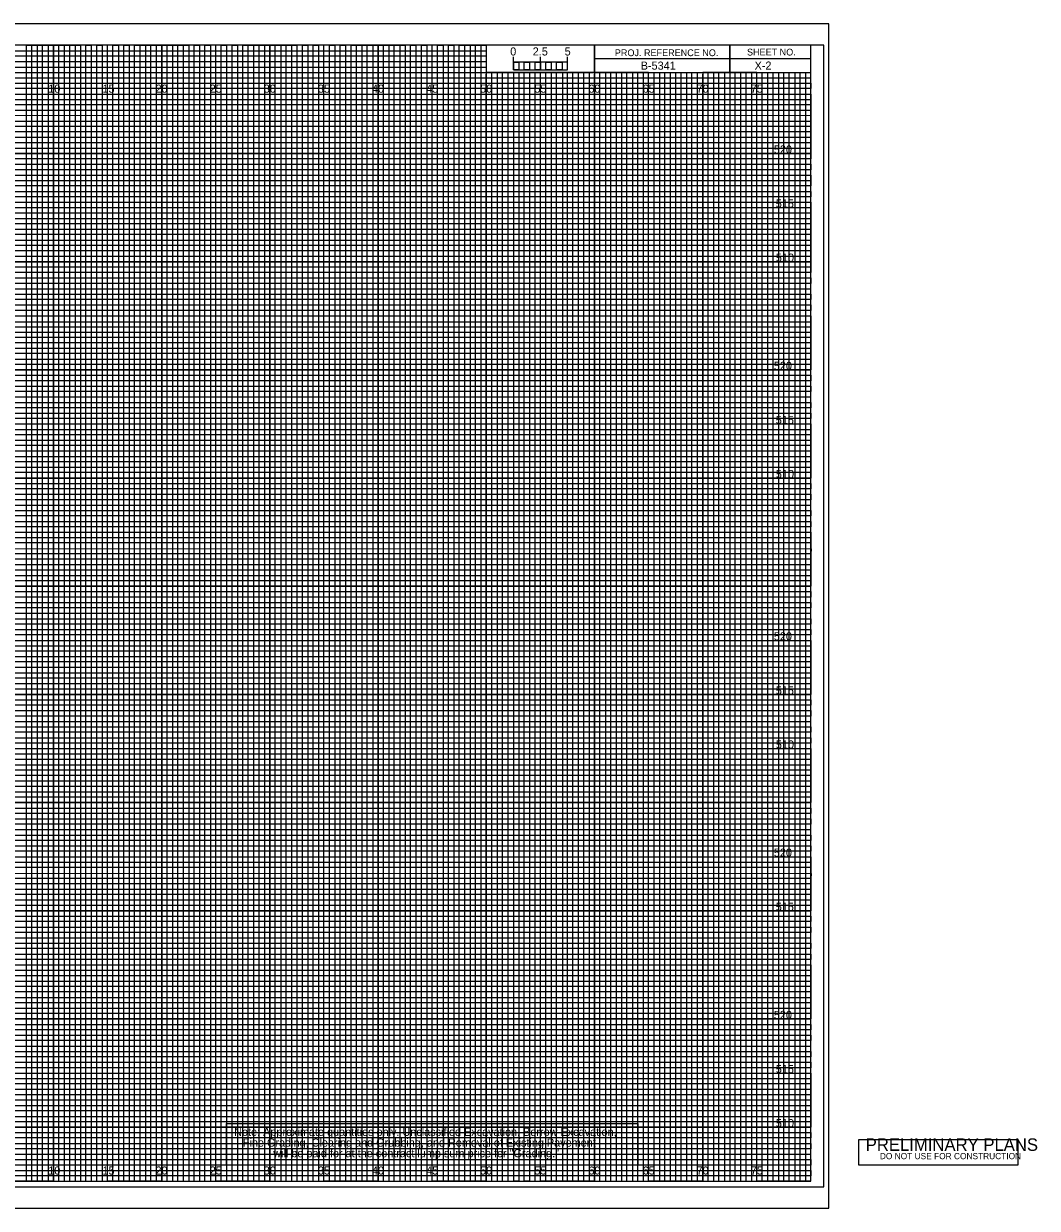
# Model space of a CAD drawing. Extents: x -7 to 181, y -2 to 107.
# Drawn here: x 87.2 to 180.9, y -2.5 to 107 of the extents above; entities that cross this region are included whole.
import ezdxf

# ---------------------------------------------------------------- set-up
doc = ezdxf.new("R2010")
doc.units = 0
for name, color, linetype in [('Prop Grid Mask', 7, 'Continuous'), ('Prop XS Bar Scale Labels', 7, 'Continuous'), ('Prop XS Elevation Labels', 7, 'Continuous'), ('Prop XS Offset Labels', 7, 'Continuous'), ('Prop XS Project Number', 7, 'Continuous'), ('Prop XS Sheet Number', 7, 'Continuous'), ('Prop XSC Text', 7, 'Continuous'), ('Sheet Cross Section CELL', 7, 'Continuous'), ('Sheet Cross Section Grid Major CELL', 7, 'Continuous'), ('Sheet Cross Section Grid Middle CELL', 7, 'Continuous'), ('Sheet Cross Section Grid Minor 1 CELL', 7, 'Continuous'), ('Sheet Cross Section Grid Minor 2 CELL', 7, 'Continuous'), ('Sheet Cross Section Scale CELL', 7, 'Continuous'), ('Sheet Cutting Line CELL', 7, 'Continuous'), ('Sheet DOT Grid CELL', 7, 'Continuous'), ('Sheet Plot Border Inside CELL', 7, 'Continuous'), ('Sheet Plot Border Outside CELL', 7, 'Continuous'), ('Sheet Sticker Preliminary CELL', 7, 'Continuous')]:
    doc.layers.add(name, color=color, linetype=linetype)

msp = doc.modelspace()

# ---------------------------------------------------------------- linework, layer by layer
at = {"layer": 'Prop Grid Mask'}
msp.add_lwpolyline([(105.99, 5.34), (144, 5.34), (144, 1.5), (105.99, 1.5)], close=True, dxfattribs=at)
at = {"layer": 'Sheet Cross Section CELL'}
for p, q in [((152.5, 105), (152.5, 102.5)), ((152.5, 102.5), (152.5, 105)), ((160, 103.75), (140, 103.75)), ((140, 103.75), (140, 102.5)), ((140, 102.5), (160, 102.5))]:
    msp.add_line(p, q, dxfattribs=at)
for points in [[(160, 105), (0, 105), (0, 0), (160, 0)], [(140, 105), (130, 105), (130, 102.52), (140, 102.52)], [(160, 105), (140, 105), (140, 102.5), (160, 102.5)]]:
    msp.add_lwpolyline(points, close=True, dxfattribs=at)
at = {"layer": 'Sheet Cross Section Grid Major CELL'}
for p, q in [((95, 105), (90, 105)), ((90, 105), (90, 0)), ((95, 0), (95, 105)), ((105, 105), (100, 105)), ((100, 105), (100, 0)), ((105, 0), (105, 105)), ((115, 105), (110, 105)), ((110, 105), (110, 0)), ((115, 0), (115, 105)), ((125, 105), (120, 105)), ((120, 105), (120, 0)), ((125, 0), (125, 105)), ((130, 105), (130, 0)), ((135, 0), (135, 102.5)), ((145, 102.5), (140, 102.5)), ((140, 102.5), (140, 0)), ((145, 0), (145, 102.5)), ((155, 102.5), (150, 102.5)), ((150, 102.5), (150, 0)), ((155, 0), (155, 102.5)), ((90, 0), (85, 0)), ((100, 0), (95, 0)), ((110, 0), (105, 0)), ((120, 0), (115, 0)), ((130, 0), (125, 0)), ((140, 0), (135, 0)), ((150, 0), (145, 0)), ((160, 0), (155, 0)), ((160, 0), (160, 0))]:
    msp.add_line(p, q, dxfattribs=at)
for points in [[(0, 100), (160, 100), (160, 95), (0, 95)], [(0, 90), (160, 90), (160, 85), (0, 85)], [(0, 80), (160, 80), (160, 75), (0, 75)], [(0, 70), (160, 70), (160, 65), (0, 65)], [(0, 60), (160, 60), (160, 55), (0, 55)], [(0, 50), (160, 50), (160, 45), (0, 45)], [(0, 40), (160, 40), (160, 35), (0, 35)], [(0, 30), (160, 30), (160, 25), (0, 25)], [(0, 20), (160, 20), (160, 15), (0, 15)], [(0, 10), (160, 10), (160, 5), (0, 5)]]:
    msp.add_lwpolyline(points, dxfattribs=at)
at = {"layer": 'Sheet Cross Section Grid Middle CELL'}
for points in [[(82.5, 0), (87.5, 0), (87.5, 105), (92.5, 105), (92.5, 0), (97.5, 0), (97.5, 105), (102.5, 105), (102.5, 0), (107.5, 0), (107.5, 105), (112.5, 105), (112.5, 0), (117.5, 0), (117.5, 105), (122.5, 105), (122.5, 0), (127.5, 0), (127.5, 105), (129.97, 105), (130, 105), (130, 102.5), (132.5, 102.5), (132.5, 0), (137.5, 0), (137.5, 102.5), (142.5, 102.5), (142.5, 0), (147.5, 0), (147.5, 102.5), (152.5, 102.5), (152.5, 0), (157.5, 0), (157.5, 102.5)], [(0, 102.5), (137.5, 102.5)], [(0, 92.5), (160, 92.5), (160, 97.5), (0, 97.5)], [(0, 82.5), (160, 82.5), (160, 87.5), (0, 87.5)], [(0, 72.5), (160, 72.5), (160, 77.5), (0, 77.5)], [(0, 62.5), (160, 62.5), (160, 67.5), (0, 67.5)], [(0, 52.5), (160, 52.5), (160, 57.5), (0, 57.5)], [(0, 42.5), (160, 42.5), (160, 47.5), (0, 47.5)], [(0, 32.5), (160, 32.5), (160, 37.5), (0, 37.5)], [(0, 22.5), (160, 22.5), (160, 27.5), (0, 27.5)], [(0, 12.5), (160, 12.5), (160, 17.5), (0, 17.5)], [(0, 2.5), (160, 2.5), (160, 7.5), (0, 7.5)]]:
    msp.add_lwpolyline(points, dxfattribs=at)
at = {"layer": 'Sheet Cross Section Grid Minor 1 CELL'}
for p, q in [((0, 104.5), (130, 104.5)), ((130, 104.5), (130, 103.99)), ((130, 103.99), (0, 103.99)), ((0, 103.5), (130, 103.5)), ((130, 102.95), (0, 102.95)), ((130, 103.5), (130, 102.95)), ((0, 102), (160, 102))]:
    msp.add_line(p, q, dxfattribs=at)
for points in [[(0, 101.5), (135, 101.5), (160, 101.5), (160, 101), (0, 101)], [(0, 100.5), (160, 100.5), (160, 99.5), (0, 99.5)], [(0, 99), (160, 99), (160, 98.5), (0, 98.49)], [(0, 98), (160, 98), (160, 97), (0, 97)], [(0, 96.5), (160, 96.5), (160, 96), (0, 96)], [(0, 95.5), (160, 95.5), (160, 94.5), (0, 94.5)], [(0, 94), (160, 94), (160, 93.5), (0, 93.5)], [(0, 93), (160, 93), (160, 92), (0, 92)], [(0, 91.5), (160, 91.5), (160, 91), (0, 91)], [(0, 90.5), (160, 90.5), (160, 89.5), (0, 89.5)], [(0, 89), (160, 89), (160, 88.5), (0, 88.5)], [(0, 88), (160, 88), (160, 86.98), (160, 86.5), (160, 86), (0, 86)], [(0, 87), (160, 87), (160, 86.5), (0, 86.5)], [(0, 85.5), (160, 85.5), (160, 84.5), (0, 84.52)], [(0, 84.52), (160, 84.5), (160, 84), (0, 84)], [(0, 83.5), (160, 83.5), (160, 83), (0, 83)], [(0, 82), (160, 82), (160, 81.5), (0, 81.5)], [(0, 81), (160, 81), (160, 80.5), (0, 80.5)], [(-0.04, 79.45), (160, 79.45), (160, 78.94), (-0.04, 78.94)], [(0, 78.5), (160, 78.5), (160, 78), (0, 78)], [(0, 77), (160, 77), (160, 76.5), (0, 76.5)], [(0, 76), (160, 76), (160, 75.5), (0, 75.5)], [(0, 74.5), (160, 74.5), (160, 74), (0, 74)], [(0, 73.5), (160, 73.5), (160, 73), (0, 73)], [(0, 72), (160, 72), (160, 71.5), (0, 71.5)], [(0, 71), (160, 71), (160, 70.5), (0, 70.5)], [(0, 69.5), (160, 69.5), (160, 68.99), (0, 69)], [(0, 68.5), (160, 68.5), (160, 68), (0, 68)], [(0, 67), (160, 67), (160, 66.5), (0, 66.5)], [(0, 66), (160, 66), (160, 65.5), (0, 65.5)], [(0, 64.5), (160, 64.5), (160, 64), (0, 64)], [(0, 63.5), (160, 63.5), (160, 63), (0, 63)], [(0, 62), (160, 62), (160, 61.5), (0, 61.5)], [(0, 61), (160, 61), (160, 60.5), (0, 60.5)], [(0, 59.5), (160, 59.5), (160, 59), (0, 59)], [(0, 58.5), (160.03, 58.45), (160, 58), (0, 58)], [(0, 57), (160, 57), (160, 56.5), (0, 56.5)], [(0, 56), (160, 56), (160, 55.5), (0, 55.5)], [(0, 54.5), (160, 54.5), (160, 54), (0, 54)], [(0, 53.5), (160, 53.5), (160, 53), (0, 53)], [(0, 52), (160, 52), (160, 51.5), (0, 51.5)], [(0, 51), (160, 51), (160, 50.5), (0, 50.5)], [(0, 49.5), (160, 49.5), (160, 49), (0, 49)], [(0, 48.5), (160, 48.5), (160, 48), (0, 48)], [(0, 47), (160, 47), (160, 46.5), (0, 46.5)], [(0, 46), (160, 46), (160, 45.5), (0, 45.5)], [(0, 44.5), (160, 44.5), (160, 44), (0, 44)], [(0, 43.5), (160, 43.5), (160, 43), (0, 43)], [(0, 42), (160, 42), (160, 41.5), (0, 41.5)], [(0, 41), (160, 41), (160, 40.5), (0, 40.5)], [(0, 39.5), (160, 39.5), (160, 38.99), (0, 39)], [(0, 38.5), (160, 38.5), (160, 38), (0, 38)], [(0, 37), (160, 37), (160, 36.5), (0, 36.5)], [(0, 36), (160, 36), (160, 35.5), (0, 35.5)], [(0, 34.5), (160, 34.5), (160, 34), (0, 34)], [(0, 33.5), (160, 33.5), (160, 33), (0, 33)], [(0, 32), (160, 32), (160, 31.5), (0, 31.5)], [(0, 31), (160, 31), (160, 30.5), (0, 30.5)], [(0, 29.5), (160, 29.5), (160, 29), (0, 29)], [(0, 28.5), (160.03, 28.46), (160, 28), (0, 28)], [(0, 27), (160, 27), (160, 26.5), (0, 26.5)], [(0, 26), (160, 26), (160, 25.5), (0, 25.5)], [(0, 24.5), (160, 24.5), (160, 24), (0, 24)], [(0, 23.5), (160, 23.5), (160, 23), (0, 23)], [(0, 22), (160, 22), (160, 21.5), (0, 21.5)], [(0, 21), (160, 21), (160, 20.5), (0, 20.5)], [(0, 19.5), (160, 19.5), (160, 19), (0, 19)], [(0, 18.5), (160, 18.5), (160, 18), (0, 18)], [(0, 17), (160, 17), (160, 16.5), (0, 16.5)], [(0, 16), (160, 16), (160, 15.5), (0, 15.5)], [(0, 14.5), (160, 14.5), (160, 14), (0, 14)], [(0, 13.5), (160, 13.5), (160, 13), (0, 13)], [(0, 12), (160, 12), (160, 11.5), (0, 11.5)], [(0, 11), (160, 11), (160, 10.5), (0, 10.5)], [(0, 9.5), (160, 9.5), (160, 9), (0, 9)], [(0, 8.5), (160, 8.5), (160, 8), (0, 8)], [(0, 7), (160, 7), (160, 6.5), (0, 6.5)], [(0, 6), (160, 6), (160, 5.5), (0, 5.5)], [(0, 4.5), (160, 4.5), (160, 4), (0, 4)], [(0, 3.5), (160, 3.5), (160, 3), (0, 3)], [(0, 2), (160, 2), (160, 1.5), (0, 1.5)], [(0, 1), (160, 1), (160, 0.5), (0, 0.5)]]:
    msp.add_lwpolyline(points, dxfattribs=at)
at = {"layer": 'Sheet Cross Section Grid Minor 2 CELL'}
for p, q in [((133.5, 102.5), (133, 102.5)), ((133, 102.5), (133, 0)), ((133.5, 0), (133.5, 102.5)), ((134.5, 102.5), (134, 102.5)), ((134, 102.5), (134, 0)), ((134.5, 0), (134.5, 102.5)), ((133, 0), (132.5, 0)), ((134, 0), (133.5, 0))]:
    msp.add_line(p, q, dxfattribs=at)
for points in [[(87.5, 0), (88, 0), (88, 105), (88.5, 105), (88.5, 0)], [(88.5, 0), (89, 0), (89, 105), (89.5, 105), (89.5, 0)], [(90, 0), (90.5, 0), (90.5, 105), (91, 105), (91, 0)], [(91, 0), (91.5, 0), (91.5, 105), (92, 105), (92, 0)], [(92.5, 0), (93, 0), (93, 105), (93.5, 105), (93.5, 0)], [(93.5, 0), (94, 0), (94, 105), (94.5, 105), (94.5, 0)], [(95, 0), (95.5, 0), (95.5, 105), (96, 105), (96, 0)], [(96, 0), (96.5, 0), (96.5, 105), (97, 105), (97, 0)], [(97.5, 0), (98, 0), (98, 105), (98.5, 105), (98.5, 0)], [(98.5, 0), (99, 0), (99, 105), (99.5, 105), (99.5, 0)], [(100, 0), (100.5, 0), (100.5, 105), (101, 105), (101, 0)], [(101, 0), (101.5, 0), (101.5, 105), (102, 105), (102, 0)], [(102.5, 0), (103, 0), (103, 105), (103.5, 105), (103.5, 0)], [(103.5, 0), (104, 0), (104, 105), (104.5, 105), (104.5, 0)], [(105, 0), (105.5, 0), (105.5, 105), (106, 105), (106, 0)], [(106, 0), (106.5, 0), (106.5, 105), (107, 105), (107, 0)], [(107.5, 0), (108, 0), (108, 105), (108.5, 105), (108.5, 0)], [(108.5, 0), (109, 0), (109, 105), (109.5, 105), (109.5, 0)], [(110, 0), (110.5, 0), (110.5, 105), (111, 105), (111, 0)], [(111, 0), (111.5, 0), (111.5, 105), (112, 105), (112, 0)], [(112.5, 0), (113, 0), (113, 105), (113.5, 105), (113.5, 0)], [(113.5, 0), (114, 0), (114, 105), (114.5, 105), (114.5, 0)], [(115, 0), (115.5, 0), (115.5, 105), (116, 105), (116, 0)], [(116, 0), (116.5, 0), (116.5, 105), (117, 105), (117, 0)], [(117.5, 0), (118, 0), (118, 105), (118.5, 105), (118.5, 0)], [(118.5, 0), (119, 0), (119, 105), (119.5, 105), (119.5, 0)], [(120, 0), (120.5, 0), (120.5, 105), (121, 105), (121, 0)], [(121, 0), (121.5, 0), (121.5, 105), (122, 105), (122, 0)], [(122.5, 0), (123, 0), (123, 105), (123.5, 105), (123.5, 0)], [(123.5, 0), (124, 0), (124, 105), (124.5, 105), (124.5, 0)], [(125, 0), (125.5, 0), (125.5, 105), (126, 105), (126, 0)], [(126, 0), (126.5, 0), (126.5, 105), (127, 105), (127, 0)], [(127.5, 0), (128, 0), (128, 105), (128.5, 105), (128.5, 0)], [(128.5, 0), (129, 0), (129, 105), (129.5, 105), (129.5, 0)], [(130, 0), (130.5, 0), (130.5, 102.5), (131.01, 102.5), (131.01, 0)], [(131, 0), (131.5, 0), (131.5, 102.5), (132, 102.5), (132, 0)], [(135, 0), (135.49, 0), (135.49, 102.5), (136, 102.5), (136, 0)], [(136, 0), (136.5, 0), (136.5, 102.5), (137.03, 102.5), (137.03, 0)], [(137.5, 0), (138, 0), (138, 102.5), (138.5, 102.5), (138.5, 0)], [(138.5, 0), (139, 0), (139, 102.5), (139.5, 102.5), (139.5, 0)], [(140, 0), (140.5, 0), (140.5, 102.5), (141, 102.5), (141, 0)], [(141, 0), (141.5, 0), (141.5, 102.5), (142, 102.5), (142, 0)], [(142.5, 0), (143, 0), (143, 102.5), (143.5, 102.5), (143.5, 0)], [(143.5, 0), (144, 0), (144, 102.5), (144.5, 102.5), (144.5, 0)], [(145, 0), (145.5, 0), (145.5, 102.5), (146, 102.5), (146, 0)], [(146, 0), (146.5, 0), (146.5, 102.5), (147, 102.5), (147, 0)], [(147.5, 0), (148, 0), (148, 102.5), (148.5, 102.5), (148.5, 0)], [(148.5, 0), (149, 0), (149, 102.5), (149.5, 102.5), (149.5, 0)], [(150, 0), (150.5, 0), (150.5, 102.5), (151, 102.5), (151, 0)], [(151, 0), (151.5, 0), (151.5, 102.5), (152, 102.5), (152, 0)], [(152.5, 0), (153, 0), (153, 102.5), (153.5, 102.5), (153.5, 0)], [(153.5, 0), (154, 0), (154, 102.5), (154.5, 102.5), (154.5, 0)], [(155, 0), (155.5, 0), (155.5, 102.5), (156, 102.5), (156, 0)], [(156, 0), (156.5, 0), (156.5, 102.5), (157, 102.5), (157, 0)], [(157.5, 0), (158, 0), (158, 102.5), (158.5, 102.5), (158.5, 0)], [(158.5, 0), (159, 0), (159, 102.5), (159.5, 102.5), (159.5, 0)]]:
    msp.add_lwpolyline(points, dxfattribs=at)
at = {"layer": 'Sheet Cross Section Scale CELL'}
for p, q in [((132.5, 102.75), (132.5, 103.95)), ((132.5, 103.45), (132.5, 103.95)), ((135, 102.75), (135, 103.95)), ((137.5, 102.75), (137.5, 103.95)), ((137.5, 103.45), (137.5, 103.95))]:
    msp.add_line(p, q, dxfattribs=at)
for points in [[(137.5, 103.45), (132.5, 103.45), (132.5, 102.75), (137.5, 102.75)], [(132.5, 103.45), (133, 103.45), (133, 102.75), (132.5, 102.75)], [(133.5, 103.45), (134, 103.45), (134, 102.75), (133.5, 102.75)], [(134.5, 103.45), (135, 103.45), (135, 102.75), (134.5, 102.75)], [(135.5, 103.45), (136, 103.45), (136, 102.75), (135.5, 102.75)], [(136.5, 103.45), (137, 103.45), (137, 102.75), (136.5, 102.75)]]:
    msp.add_lwpolyline(points, close=True, dxfattribs=at)
at = {"layer": 'Sheet Cutting Line CELL'}
for p, q in [((161.65, 107), (-6.7, 107)), ((-6.7, -2.5), (161.65, -2.5))]:
    msp.add_line(p, q, dxfattribs=at)
at = {"layer": 'Sheet DOT Grid CELL'}
for p, q in [((90, 0), (90, 105)), ((95, 0), (95, 105)), ((100, 0), (100, 105)), ((105, 0), (105, 105)), ((110, 0), (110, 105)), ((115, 0), (115, 105)), ((120, 0), (120, 105)), ((125, 0), (125, 105)), ((130, 0), (130, 102.34)), ((135, 0), (135, 102.34)), ((140, 0), (140, 102.34)), ((145, 0), (145, 102.34)), ((150, 0), (150, 102.34)), ((155, 0), (155, 102.34)), ((0, 100), (160, 100)), ((0, 95), (160, 95)), ((0, 90), (160, 90)), ((0, 85), (160, 85)), ((0, 80), (160, 80)), ((0, 75), (160, 75)), ((0, 70), (160, 70)), ((0, 65), (160, 65)), ((0, 60), (160, 60)), ((0, 55), (160, 55)), ((0, 50), (160, 50)), ((0, 45), (160, 45)), ((0, 40), (160, 40)), ((0, 35), (160, 35)), ((0, 30), (160, 30)), ((0, 25), (160, 25)), ((0, 20), (160, 20)), ((0, 15), (160, 15)), ((0, 10), (160, 10)), ((0, 5), (160, 5))]:
    msp.add_line(p, q, dxfattribs=at)
at = {"layer": 'Sheet Plot Border Inside CELL'}
msp.add_lwpolyline([(-5.4, -0.5), (161.2, -0.5), (161.2, 105), (-5.4, 105)], close=True, dxfattribs=at)
at = {"layer": 'Sheet Plot Border Outside CELL'}
msp.add_lwpolyline([(-6.7, -2.5), (161.65, -2.5), (161.65, 107), (-6.7, 107)], close=True, dxfattribs=at)
at = {"layer": 'Sheet Sticker Preliminary CELL'}
msp.add_lwpolyline([(164.41, 1.5), (164.41, 3.85), (179.11, 3.85), (179.11, 1.5)], close=True, dxfattribs=at)

# ---------------------------------------------------------------- texts
at = {"layer": 'Prop XS Bar Scale Labels'}
for s, p in [('2.5', (134.29, 104.06)), ('5', (137.24, 104.06))]:
    msp.add_text(s, height=0.75, dxfattribs=at).set_placement(p)
at = {"layer": 'Prop XS Elevation Labels'}
for s, p in [('520', (156.57, 95)), ('515', (156.75, 90)), ('510', (156.76, 85)), ('520', (156.57, 75)), ('515', (156.75, 70)), ('510', (156.76, 65)), ('520', (156.57, 50)), ('515', (156.75, 45)), ('510', (156.76, 40)), ('520', (156.57, 30)), ('515', (156.75, 25)), ('520', (156.57, 15)), ('515', (156.75, 10)), ('510', (156.76, 5))]:
    msp.add_text(s, height=0.75, dxfattribs=at).set_placement(p)
at = {"layer": 'Prop XS Offset Labels'}
for s, p in [('10', (89.52, 100.62)), ('15', (94.53, 100.62)), ('20', (99.43, 100.62)), ('25', (104.44, 100.62)), ('30', (109.43, 100.62)), ('35', (114.44, 100.62)), ('40', (119.43, 100.62)), ('45', (124.44, 100.62)), ('50', (129.43, 100.62)), ('55', (134.44, 100.62)), ('60', (139.43, 100.62)), ('65', (144.44, 100.62)), ('70', (149.43, 100.62)), ('75', (154.44, 100.62)), ('10', (89.52, 0.62)), ('15', (94.53, 0.62)), ('20', (99.43, 0.62)), ('25', (104.44, 0.62)), ('30', (109.43, 0.62)), ('35', (114.44, 0.62)), ('40', (119.43, 0.62)), ('45', (124.44, 0.62)), ('50', (129.43, 0.62)), ('55', (134.44, 0.62)), ('60', (139.43, 0.62)), ('65', (144.44, 0.62)), ('70', (149.43, 0.62)), ('75', (154.44, 0.62))]:
    msp.add_text(s, height=0.75, dxfattribs=at).set_placement(p)
at = {"layer": 'Prop XS Project Number'}
msp.add_text('B-5341', height=0.75, dxfattribs=at).set_placement((144.27, 102.75))
at = {"layer": 'Prop XS Sheet Number'}
msp.add_text('X-2', height=0.75, dxfattribs=at).set_placement((154.79, 102.75))
at = {"layer": 'Prop XSC Text'}
for s, p in [('Note: Approximate quantities only. Unclassified Excavation, Borrow Excavation, ', (106.7, 4.19)), ('    Fine Grading, Clearing and Grubbing, and Removal of Existing Pavement', (106.39, 3.2)), ('will be paid for at the contract lump sum price for "Grading."', (110.31, 2.22))]:
    msp.add_text(s, height=0.75, dxfattribs=at).set_placement(p)
at = {"layer": 'Sheet Cross Section CELL'}
for s, p in [('PROJ. REFERENCE NO.', (141.88, 104)), ('SHEET NO.', (154.09, 104.06))]:
    msp.add_text(s, height=0.625, dxfattribs=at).set_placement(p)
at = {"layer": 'Sheet Cross Section Scale CELL'}
msp.add_text('0', height=0.75, dxfattribs=at).set_placement((132.21, 104.06))
at = {"layer": 'Sheet Sticker Preliminary CELL'}
for s, height, p in [('PRELIMINARY PLANS', 1.152, (165.06, 2.81)), ('DO NOT USE FOR CONSTRUCTION', 0.576, (166.37, 2.04))]:
    msp.add_text(s, height=height, dxfattribs=at).set_placement(p)

doc.saveas('drawing.dxf')
